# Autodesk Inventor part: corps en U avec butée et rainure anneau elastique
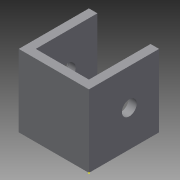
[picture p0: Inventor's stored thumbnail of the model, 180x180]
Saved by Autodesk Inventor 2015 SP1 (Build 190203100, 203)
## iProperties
Created: 2015-01
Part Number: corps en U avec butée et rainure anneau elastique
Material: Générique
Document SubType Name: Modeling
Designer: Dominique
Density: 1 g/cm^3
Appearance: Par défaut
Author: Dominique
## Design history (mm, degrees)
sketch "Esquisse1"
  geometry: L1 (0, 0)-(-66, 0); L2 (-66, 0)-(-66, 68); L3 (0, 68)-(0, 0); L4 (-8, 68)-(-8, 8); L5 (-8, 8)-(-58, 8); L6 (-58, 8)-(-58, 68); L7 (-66, 68)-(-58, 68); L8 (-8, 68)-(0, 68)
  constraints: 16 end point, 4 parallel, 1 horizontal, 1 perpendicular
  dimensions: "d0" = 8 distance between parallel lines of L3 L4; "d1" = 8 distance between parallel lines of L1 L5 (= d0); "d2" = 8 distance between parallel lines of L6 L2 (= d0); "d3" = 68 distance between parallel lines of L1 L7 (computed from d0); "d4" = 68 distance from line of L3.start L1 (= d3); "d5" = 66 distance between parallel lines of L3 L2 (computed from d0)
extrude "Extrusion1" new body sketch "Esquisse1" distance "d6" = 68 (= d3); taper "d7" = 0 deg
sketch "Esquisse2"
  geometry: 1 further point
chamfer "Chanfrein1" distance "d8" = 2; stored, may be unused: second distance "d9" = 2, angle "d10" = 45 deg
sketch "Esquisse3"
  geometry: L1 (66, 68)-(2, 68) reference; C1 r 7.5 at (34, 38); 1 further point
  constraints: 1 centre point
  dimensions: "d11" = 15 diameter of C1; "d12" = 30 distance from line of L1 C1.centre
extrude "Extrusion2" cut sketch "Esquisse3" distance "d13" = 65; taper "d14" = 0 deg
sketch "Esquisse4"
  geometry: C1 r 7 at (0, 0); 1 further point
  constraints: 1 centre point
  dimensions: "d15" = 14 diameter of C1
extrude "Extrusion3" cut sketch "Esquisse4" stored distance "d16" = 65; taper "d17" = 0 deg
node "Plan de construction1"
sketch "Esquisse5"
  geometry: C1 r 7 at (34, 38) reference; C2 r 7.85 at (34, 38); 1 further point
  constraints: 1 centre point, 1 coincident
  dimensions: "d19" = 15.7 diameter of C2
extrude "Extrusion4" cut sketch "Esquisse5" distance "d20" = 1; taper "d21" = 0 deg
node "Solide1"
other parameters: "d18" = -1
